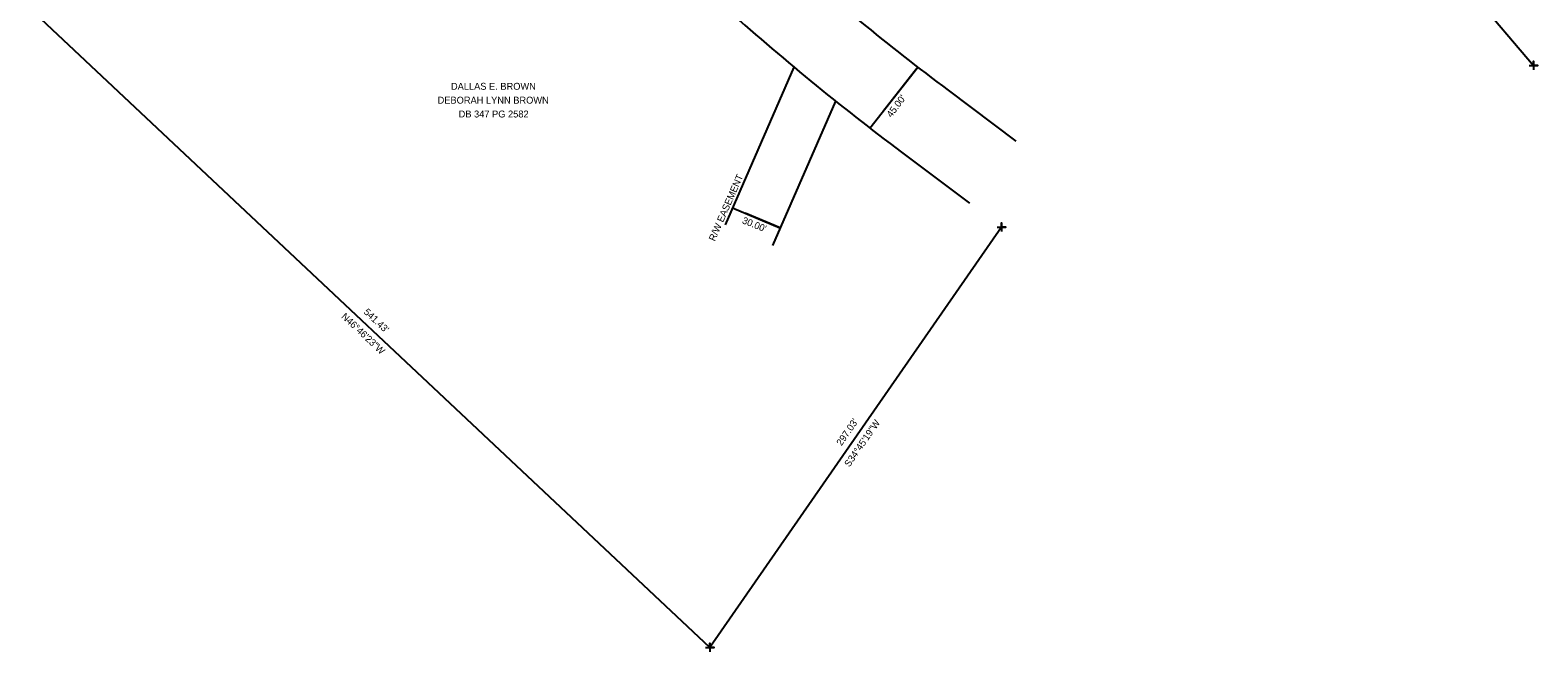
# Model space of a CAD drawing. Extents: x 1121294 to 1124558, y 901107 to 903080.
# Drawn here: x 1122905 to 1123780, y 901107 to 901468 of the extents above; entities that cross this region are included whole.
import ezdxf

# ---------------------------------------------------------------- set-up
doc = ezdxf.new("R2010")
doc.units = 0
for name, color, linetype in [('CTL Primary Horizontal and Vertical CELL', 7, 'Continuous'), ('CTL Secondary Horizontal and Vertical CELL', 7, 'Continuous'), ('CTL Vertical Benchmark CELL', 7, 'Continuous'), ('Default Symbol CELL', 7, 'Continuous'), ('Exist DTM Regular Point CELL', 7, 'Continuous'), ('Exist Survey Control Group', 7, 'Continuous'), ('Exist Survey Observation Group', 7, 'Continuous'), ('Exist Utilities Power Pole CELL', 7, 'Continuous')]:
    doc.layers.add(name, color=color, linetype=linetype)

msp = doc.modelspace()

# ---------------------------------------------------------------- linework, layer by layer
at = {"layer": 'CTL Secondary Horizontal and Vertical CELL'}
for p, q in [((1123563.45, 901699.08), (1123777.92, 901447.1)), ((1123299.8, 901109.21), (1122905.29, 901480.03)), ((1123469.13, 901353.25), (1123299.8, 901109.21))]:
    msp.add_line(p, q, dxfattribs=at)
at = {"layer": 'CTL Vertical Benchmark CELL'}
for p, q in [((1123777.92, 901447.1), (1123777.92, 901447.1)), ((1123469.13, 901353.25), (1123469.13, 901353.25)), ((1123299.8, 901109.21), (1123299.8, 901109.21))]:
    msp.add_line(p, q, dxfattribs=at)
for points in [[(1123775.42, 901447.1), (1123780.42, 901447.1), (1123777.92, 901447.1), (1123777.92, 901449.6), (1123777.92, 901444.6)], [(1123466.63, 901353.25), (1123471.63, 901353.25), (1123469.13, 901353.25), (1123469.13, 901355.75), (1123469.13, 901350.75)], [(1123297.3, 901109.21), (1123302.3, 901109.21), (1123299.8, 901109.21), (1123299.8, 901111.71), (1123299.8, 901106.71)]]:
    msp.add_lwpolyline(points, dxfattribs=at)
at = {"layer": 'Default Symbol CELL'}
msp.add_line((1123411.08, 901396.74), (1123450.45, 901367.24), dxfattribs=at)
msp.add_arc((1124324.04, 902615.15), 1522.5, 228.11275, 233.15592, dxfattribs=at)
at = {"layer": 'Exist DTM Regular Point CELL'}
for p, q in [((1123348.58, 901446.18), (1123308.61, 901354.54)), ((1123438.07, 901432.75), (1123477.44, 901403.26)), ((1123372.71, 901426.46), (1123336.11, 901342.55))]:
    msp.add_line(p, q, dxfattribs=at)
msp.add_arc((1124324.04, 902615.15), 1477.5, 228.11275, 233.15592, dxfattribs=at)
at = {"layer": 'Exist Survey Control Group'}
for p, q in [((1123392.75, 901410.7), (1123420.58, 901446.07)), ((1123420.6, 901446.04), (1123400.17, 901420.13)), ((1123312.96, 901364.52), (1123340.5, 901352.86)), ((1123340.58, 901352.8), (1123320.31, 901361.4))]:
    msp.add_line(p, q, dxfattribs=at)

# ---------------------------------------------------------------- texts
at = {"layer": 'CTL Primary Horizontal and Vertical CELL'}
for s, rotation, p in [("45.00'", 52.99895, (1123405.19, 901416.57)), ("30.00'", 338.23999, (1123318.2, 901355.63))]:
    msp.add_text(s, height=4.02, rotation=rotation, dxfattribs=at).set_placement(p)
at = {"layer": 'Exist Survey Observation Group'}
for s, p in [('DALLAS E. BROWN', (1123149.54, 901433)), ('DEBORAH LYNN BROWN', (1123141.79, 901424.96)), ('DB 347 PG 2582', (1123153.98, 901416.92))]:
    msp.add_text(s, height=4.02, dxfattribs=at).set_placement(p)
for s, rotation, p in [("541.43'", 316.773, (1123098.58, 901303.53)), ('N46°46\'23"W', 316.773, (1123085.59, 901300.92)), ("297.03'", 55.24479, (1123376.23, 901226)), ('S34°45\'19"W', 55.24479, (1123380.81, 901213.66))]:
    msp.add_text(s, height=4.02, rotation=rotation, dxfattribs=at).set_placement(p)
at = {"layer": 'Exist Utilities Power Pole CELL'}
msp.add_text('R/W EASEMENT', height=4.02, rotation=66.43489, dxfattribs=at).set_placement((1123302.68, 901344.77))

doc.saveas('drawing.dxf')
